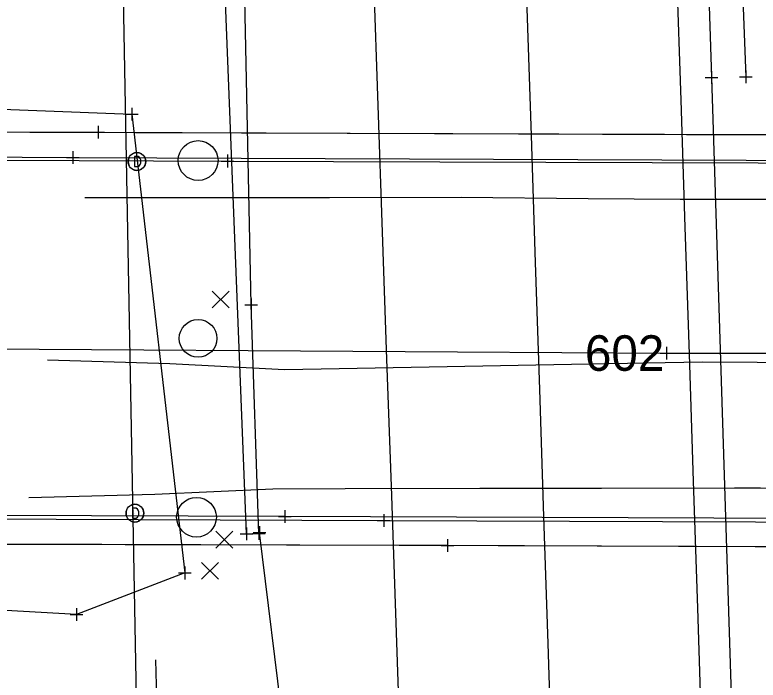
# Model space of a CAD drawing. Extents: x 146022 to 147632, y 437624 to 440659.
# Drawn here: x 146910.1 to 146968.6, y 438601.8 to 438654.2 of the extents above; entities that cross this region are included whole.
import ezdxf

# ---------------------------------------------------------------- set-up
doc = ezdxf.new("R2010")
doc.units = 0
for name, color, linetype in [('_CIVIL_CONSTRUCTION', 7, 'Continuous'), ('BR_X_SV_Bottom_of_Beam', 7, 'Continuous'), ('BR_X_SV_Pier', 7, 'Continuous'), ('Default', 7, 'Continuous'), ('DR_P_Underdrain', 7, 'Continuous'), ('DR_X_Cells', 7, 'Continuous'), ('DR_X_Storm_Sewer', 7, 'Continuous'), ('DR_X_Text', 7, 'Continuous'), ('DT_X_Triangles', 7, 'Continuous'), ('GE_P_Alignment_100_Cardinal_Points', 7, 'Continuous'), ('GE_P_Alignment_100_Stations', 7, 'Continuous'), ('PF_X_Ground_Line', 7, 'Continuous'), ('PV_P_Curb', 7, 'Continuous'), ('RD_P_Anchor_Assembly', 7, 'Continuous'), ('RD_P_GR_Lt_Replaced', 7, 'Continuous'), ('SC_Scratch3', 7, 'Continuous'), ('SH_Text', 7, 'Continuous'), ('SV_X_Terrain_Boundary', 7, 'Continuous'), ('UT_X_Electric', 7, 'Continuous')]:
    doc.layers.add(name, color=color, linetype=linetype)

msp = doc.modelspace()

# ---------------------------------------------------------------- linework, layer by layer
at = {"layer": '_CIVIL_CONSTRUCTION'}
for p, q in [((146925.598, 438631.121), (146926.932, 438632.456)), ((146925.598, 438632.456), (146926.932, 438631.121)), ((146925.882, 438612.202), (146927.215, 438613.537)), ((146925.882, 438613.537), (146927.215, 438612.202)), ((146924.767, 438609.76), (146926.1, 438611.095)), ((146924.767, 438611.095), (146926.1, 438609.76))]:
    msp.add_line(p, q, dxfattribs=at)
at = {"layer": 'BR_X_SV_Bottom_of_Beam'}
for points in [[(146915.587, 438639.808), (146925.317, 438639.819), (146934.821, 438639.83), (146945.2, 438639.842), (146955.198, 438639.747), (146962.426, 438639.678), (146972.429, 438639.685), (146982.304, 438639.693), (147002.305, 438639.484), (147008.894, 438639.416), (147018.894, 438639.375), (147029.574, 438639.335), (147038.394, 438639.296), (147048.275, 438639.31), (147058.405, 438639.324), (147060.13, 438639.326)], [(147060.147, 438626.995), (147049.92, 438626.917), (147040.15, 438626.842), (147030.152, 438626.766), (147020.152, 438626.69), (147010.154, 438626.614), (147008.517, 438626.602), (146998.516, 438626.658), (146988.288, 438626.717), (146978.515, 438626.772), (146968.486, 438626.829), (146964.186, 438626.853), (146953.877, 438626.667), (146944.082, 438626.48), (146934.171, 438626.293), (146931.304, 438626.257), (146922.277, 438626.712), (146912.643, 438627.012)], [(147060.393, 438616.42), (147050.239, 438616.494), (147040.369, 438616.566), (147033.157, 438616.619), (147023.159, 438616.592), (147013.16, 438616.565), (147008.681, 438616.553), (146998.682, 438616.645), (146988.669, 438616.737), (146978.685, 438616.83), (146968.751, 438616.922), (146966.697, 438616.94), (146956.246, 438616.918), (146946.661, 438616.897), (146936.054, 438616.876), (146930.378, 438616.865), (146921.088, 438616.438), (146911.185, 438616.183)]]:
    msp.add_lwpolyline(points, dxfattribs=at)
at = {"layer": 'BR_X_SV_Pier'}
for centre, radius in [((146924.496, 438642.726), 1.569), ((146924.493, 438628.73), 1.484), ((146924.369, 438614.647), 1.563)]:
    msp.add_circle(centre, radius, dxfattribs=at)
at = {"layer": 'DR_P_Underdrain'}
msp.add_lwpolyline([(146928.298, 438613.34), (146926.368, 438662.576)], dxfattribs=at)
at = {"layer": 'DR_X_Cells'}
for points in [[(146888.686, 438647.566), (146919.282, 438646.371), (146923.453, 438610.256)], [(146923.453, 438610.256), (146914.918, 438606.992), (146888.926, 438608.466), (146888.686, 438647.566)]]:
    msp.add_lwpolyline(points, dxfattribs=at)
at = {"layer": 'DR_X_Storm_Sewer'}
msp.add_line((146918.334, 438670.001), (146920.421, 438556.953), dxfattribs=at)
at = {"layer": 'DR_X_Text'}
msp.add_line((146921.578, 438581.91), (146921.18, 438603.432), dxfattribs=at)
at = {"layer": 'DT_X_Triangles'}
for p, q in [((146919.682, 438642.654), (146919.682, 438642.654)), ((146919.682, 438642.654), (146919.682, 438642.654)), ((146919.682, 438642.654), (146919.682, 438642.654)), ((146919.682, 438642.654), (146919.682, 438642.654)), ((146919.682, 438642.654), (146919.682, 438642.654)), ((146919.522, 438614.963), (146919.522, 438614.963)), ((146919.522, 438614.963), (146919.522, 438614.963)), ((146919.522, 438614.963), (146919.522, 438614.963)), ((146919.522, 438614.963), (146919.522, 438614.963)), ((146919.522, 438614.963), (146919.522, 438614.963))]:
    msp.add_line(p, q, dxfattribs=at)
for centre in [(146919.682, 438642.654), (146919.522, 438614.963)]:
    msp.add_circle(centre, 0.7, dxfattribs=at)
at = {"layer": 'GE_P_Alignment_100_Cardinal_Points'}
for points in [[(146886.697, 438643.146), (146914.629, 438642.971), (146987.485, 438642.673), (147030.154, 438642.484), (147082.653, 438642.27), (147087.676, 438642.282), (147088.142, 438642.428), (147088.538, 438642.44)], [(146886.273, 438614.58), (146893.974, 438614.564), (146939.097, 438614.385), (146982.973, 438614.237), (147025.25, 438614.063), (147087.547, 438613.803), (147088.31, 438613.791)]]:
    msp.add_lwpolyline(points, dxfattribs=at)
at = {"layer": 'GE_P_Alignment_100_Stations'}
for points in [[(146886.617, 438645.057), (146916.632, 438644.953), (146969.533, 438644.744), (146993.171, 438644.674), (147051.149, 438644.479), (147087.815, 438644.354), (147088.055, 438644.306), (147088.543, 438644.321)], [(147088.417, 438611.938), (147085.161, 438611.927), (147048.137, 438612.028), (147009.735, 438612.191), (146980.437, 438612.254), (146944.113, 438612.41), (146906.055, 438612.508), (146890.588, 438612.592), (146885.707, 438612.644)]]:
    msp.add_lwpolyline(points, dxfattribs=at)
at = {"layer": 'PF_X_Ground_Line'}
msp.add_lwpolyline([(146951.853, 439101), (146954.034, 439043.562), (146955.672, 438986.112), (146957.925, 438928.504), (146959.866, 438869.86), (146961.604, 438814.762), (146963.442, 438771.016), (146964.929, 438718.683), (146967.586, 438649.319)], dxfattribs=at)
at = {"layer": 'PV_P_Curb'}
for points in [[(146947.673, 438732.04), (146948.032, 438722.046), (146948.392, 438712.053), (146948.751, 438702.059), (146949.11, 438692.066), (146949.376, 438684.672), (146949.705, 438674.677), (146950.034, 438664.683), (146950.362, 438654.688), (146950.691, 438644.694), (146951.02, 438634.699), (146951.348, 438624.704), (146951.677, 438614.71), (146952.006, 438604.715), (146952.335, 438594.721)], [(146887.294, 438628.027), (146961.353, 438627.571), (147033.742, 438627.551), (147087.577, 438627.48)]]:
    msp.add_lwpolyline(points, dxfattribs=at)
at = {"layer": 'RD_P_Anchor_Assembly'}
for p, q in [((146964.888, 438649.772), (146964.888, 438648.772)), ((146967.586, 438649.819), (146967.586, 438648.819)), ((146964.388, 438649.272), (146965.388, 438649.272)), ((146964.888, 438649.272), (146964.888, 438649.272)), ((146967.086, 438649.319), (146968.086, 438649.319)), ((146967.586, 438649.319), (146967.586, 438649.319)), ((146919.282, 438646.871), (146919.282, 438645.871)), ((146918.782, 438646.371), (146919.782, 438646.371)), ((146919.282, 438646.371), (146919.282, 438646.371)), ((146916.632, 438645.453), (146916.632, 438644.453)), ((146916.132, 438644.953), (146917.132, 438644.953)), ((146916.632, 438644.953), (146916.632, 438644.953)), ((146914.129, 438642.971), (146915.129, 438642.971)), ((146914.629, 438643.471), (146914.629, 438642.471)), ((146914.629, 438642.971), (146914.629, 438642.971)), ((146926.812, 438643.191), (146926.812, 438642.191)), ((146926.312, 438642.691), (146927.312, 438642.691)), ((146926.812, 438642.691), (146926.812, 438642.691)), ((146928.662, 438631.87), (146928.662, 438630.87)), ((146928.162, 438631.37), (146929.162, 438631.37)), ((146928.662, 438631.37), (146928.662, 438631.37)), ((146961.353, 438628.071), (146961.353, 438627.071)), ((146960.853, 438627.571), (146961.853, 438627.571)), ((146961.353, 438627.571), (146961.353, 438627.571)), ((146931.328, 438615.21), (146931.328, 438614.21)), ((146939.097, 438614.885), (146939.097, 438613.885)), ((146930.828, 438614.71), (146931.828, 438614.71)), ((146931.328, 438614.71), (146931.328, 438614.71)), ((146938.597, 438614.385), (146939.597, 438614.385)), ((146939.097, 438614.385), (146939.097, 438614.385)), ((146928.298, 438613.84), (146928.298, 438612.84)), ((146929.273, 438613.876), (146929.273, 438612.876)), ((146929.334, 438613.937), (146929.334, 438612.937)), ((146927.798, 438613.34), (146928.798, 438613.34)), ((146928.298, 438613.34), (146928.298, 438613.34)), ((146928.773, 438613.376), (146929.773, 438613.376)), ((146928.834, 438613.437), (146929.834, 438613.437)), ((146929.273, 438613.376), (146929.273, 438613.376)), ((146929.334, 438613.437), (146929.334, 438613.437)), ((146944.113, 438612.91), (146944.113, 438611.91)), ((146943.613, 438612.41), (146944.613, 438612.41)), ((146944.113, 438612.41), (146944.113, 438612.41)), ((146923.453, 438610.756), (146923.453, 438609.756)), ((146922.953, 438610.256), (146923.953, 438610.256)), ((146923.453, 438610.256), (146923.453, 438610.256)), ((146914.918, 438607.492), (146914.918, 438606.492)), ((146914.418, 438606.992), (146915.418, 438606.992)), ((146914.918, 438606.992), (146914.918, 438606.992))]:
    msp.add_line(p, q, dxfattribs=at)
at = {"layer": 'RD_P_GR_Lt_Replaced'}
for points in [[(146929.273, 438613.376), (146928.662, 438631.37), (146927.616, 438682.024), (146925.567, 438760.707), (146923.546, 438837.343), (146921.102, 438899.438), (146919.06, 438958.23), (146916.568, 439025.757), (146914.006, 439102.628)], [(146949.534, 439101.118), (146951.472, 439043.06), (146953.424, 438986.872), (146955.299, 438928.328), (146957.213, 438869.742), (146959.24, 438814.606), (146960.644, 438770.625), (146962.641, 438718.514), (146964.888, 438649.272), (146966.598, 438595.694)], [(146946.899, 438144.613), (146944.746, 438205.416), (146943.147, 438266.6), (146940.8, 438324.485), (146938.637, 438383.769), (146936.819, 438441.332), (146934.627, 438500.214), (146932.911, 438555.466), (146931.242, 438597.9), (146929.334, 438613.437)]]:
    msp.add_lwpolyline(points, dxfattribs=at)
at = {"layer": 'SC_Scratch3'}
for points in [[(146940.403, 438597.103), (146940.055, 438607.097), (146939.706, 438617.091), (146939.357, 438627.085), (146939.008, 438637.079), (146938.659, 438647.073), (146938.31, 438657.067), (146938.186, 438660.631), (146937.834, 438670.625), (146937.482, 438680.618), (146937.13, 438690.612), (146936.777, 438700.606), (146936.425, 438710.6), (146936.073, 438720.594), (146935.721, 438730.587)], [(146959.681, 438730.614), (146960.038, 438720.621), (146960.394, 438710.627), (146960.75, 438700.633), (146961.106, 438690.64), (146961.322, 438684.597), (146961.611, 438674.601), (146961.818, 438667.463), (146962.144, 438657.468), (146962.471, 438647.473), (146962.797, 438637.479), (146963.124, 438627.484), (146963.45, 438617.489), (146963.777, 438607.495), (146964.103, 438597.5)]]:
    msp.add_lwpolyline(points, dxfattribs=at)
at = {"layer": 'SH_Text'}
msp.add_lwpolyline([(146885.966, 438642.868), (146926.812, 438642.691), (146985.277, 438642.496), (147039.933, 438642.254), (147088.536, 438642.067), (147088.54, 438627.583), (147088.397, 438614.111), (147046.407, 438614.279), (146992.08, 438614.464), (146931.328, 438614.71), (146885.67, 438614.858), (146885.649, 438627.845)], close=True, dxfattribs=at)
at = {"layer": 'SV_X_Terrain_Boundary'}
msp.add_lwpolyline([(146885.67, 438614.858), (146885.705, 438612.644), (147088.417, 438611.938), (147088.276, 438614.389), (147088.54, 438627.583), (147088.536, 438642.067), (147088.543, 438644.321), (147051.149, 438644.479), (146993.171, 438644.674), (146969.533, 438644.744), (146886.231, 438645.023), (146885.966, 438642.868), (146885.966, 438642.868), (146885.649, 438627.845)], close=True, dxfattribs=at)
at = {"layer": 'UT_X_Electric'}
for points in [[(146919.782, 438643.054), (146919.502, 438643.054), (146919.502, 438642.254), (146919.782, 438642.254)], [(146919.622, 438615.363), (146919.342, 438615.363), (146919.342, 438614.563), (146919.622, 438614.563)]]:
    msp.add_lwpolyline(points, dxfattribs=at)
for centre, radius, start, end in [((146919.682, 438642.654), 0.7, 150.01836, 209.98164), ((146919.682, 438642.654), 0.7, 60.01836, 120.01574), ((146919.527, 438642.654), 0.474, 302.51483, 57.48517), ((146919.682, 438642.654), 0.7, 330.01836, 29.98164), ((146919.682, 438642.654), 0.7, 239.98426, 299.98164), ((146919.522, 438614.963), 0.7, 60.01836, 120.01574), ((146919.522, 438614.963), 0.7, 150.01836, 209.98164), ((146919.367, 438614.963), 0.474, 302.51483, 57.48517), ((146919.522, 438614.963), 0.7, 330.01836, 29.98164), ((146919.522, 438614.963), 0.7, 239.98426, 299.98164)]:
    msp.add_arc(centre, radius, start, end, dxfattribs=at)

# ---------------------------------------------------------------- texts
at = {"layer": 'Default'}
msp.add_text('602', height=2.8, dxfattribs=at).set_placement((146954.93, 438626.171))

doc.saveas('drawing.dxf')
